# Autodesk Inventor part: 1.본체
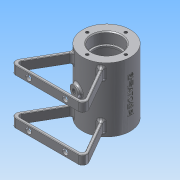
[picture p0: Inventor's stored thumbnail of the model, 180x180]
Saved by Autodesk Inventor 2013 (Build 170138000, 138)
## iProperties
Created: 2016-03
Part Number: 1.본체
Material: 알루미늄 6061
Document SubType Name: Modeling
Designer: Administrator
Mass: 211.191 g
Surface Area: 327.687 cm^2
Volume: 77.9302 cm^3
Density: 2.71 g/cm^3
Author: Administrator
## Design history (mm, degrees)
sketch "스케치1"
  geometry: C1 r 26 at (0, 0); 1 further point
  constraints: 1 centre point, 1 coincident
  dimensions: "d0" = 52 diameter of C1
extrude "돌출1" new body sketch "스케치1" stored distance "d1" = 70; taper "d2" = 0 deg
sketch "스케치2"
  geometry: C1 r 21 at (0, 0); 1 further point
  constraints: 1 centre point, 1 coincident
  dimensions: "d3" = 42 diameter of C1
extrude "돌출2" cut sketch "스케치2" stored distance "d4" = 42; taper "d5" = 0 deg
hole "구멍1" diameter "d8" = 28; stored, may be unused: countersink angle "d12" = 90 deg, drill point angle "d14" = 0 deg; dims "d6" = 10, "d7" = 10, "d9" = 6, "d10" = 32, "d11" = 12, "d13" = 8
hole "구멍2" diameter "d17" = 28; stored, may be unused: countersink angle "d21" = 90 deg, drill point angle "d23" = 0 deg; dims "d15" = 10, "d16" = 10, "d18" = 6, "d19" = 32, "d20" = 12, "d22" = 8
sketch "스케치3"
  geometry: 1 further point
sketch "스케치4" dims "d24" = 42
  geometry: C1 r 26 at (0, 0) reference; 3 further points
  constraints: 2 vertical alignment, 1 coincident, 2 other
hole "구멍3" sketch "스케치4" at (0, 21) diameter "d25" = 3.242; stored, may be unused: countersink angle "d29" = 90 deg, drill point angle "d31" = 118 deg; dims "d26" = 8, "d27" = 32, "d28" = 12, "d30" = 10
sketch "스케치5"
  geometry: 1 further point
node "작업 평면3"
sketch "스케치7"
  geometry: C1 r 5 at (0, 0); 1 further point
  constraints: 1 centre point, 1 coincident
  dimensions: "d37" = 10 diameter of C1
extrude "돌출3" join sketch "스케치7" stored distance "d38" = 42; taper "d39" = 0 deg
sketch "스케치8"
  geometry: C1 r 1.621 at (21, 0) reference; C2 r 1.621 at (0, -21) reference; C3 r 1.621 at (-21, 0) reference; C4 r 1.621 at (0, 21) reference; C5 r 16 at (0, 0) reference; C6 r 26 at (0, 0) reference
node "작업 평면4"
sketch "스케치10"
  geometry: L1 (-14.183, -21.791)-(-37.398, -62); L2 (-37.398, -62)-(37.398, -62); L3 (37.398, -62)-(14.183, -21.791); L4 (16.613, -20)-(42.594, -65); L5 (42.594, -65)-(-42.594, -65); L6 (-42.594, -65)-(-16.613, -20); L7 (0, 0)-(0, -60.192); C1 r 21 at (0, 0) reference; A1 r 26 centre (0, 0) between (-14.183, -21.791) and (14.183, -21.791) reference; 1 further point
  constraints: 14 end point, 4 point on circle, 2 equal length, 2 parallel, 1 horizontal, 1 perpendicular
  dimensions: "d41" = 30 deg angle of L7 L3; "d42" = 30 deg angle of L1 L7; "d43" = 30 deg angle of L7 L6; "d44" = 3 distance between parallel lines of L3 L4; "d46" = 65 distance from line of L5 point (0, 0); "d47" = 3 distance between parallel lines of L2 L5; "d142" = 45 distance from line of L5 L4.start
extrude "돌출4" join sketch "스케치10" distance "d48" = 10; taper "d49" = 0 deg
fillet "모깎기1" dims "d53" = 5, "d54" = 3
hole "구멍4" diameter "d57" = 4.917; stored, may be unused: countersink angle "d61" = 90 deg, drill point angle "d63" = 118 deg; dims "d55" = 10, "d56" = 10, "d58" = 8, "d59" = 32, "d60" = 12, "d62" = 17.75
sketch "스케치13"
  geometry: L1 (0, 0)-(67.868, 0) reference; L2 (0, 10)-(67.868, 10) reference; L3 (33.934, 10)-(33.934, 0); C1 r 3 at (13.934, 5); C2 r 3 at (53.934, 5); 1 further point
  constraints: 2 centre point, 2 end point, 2 midpoint
  dimensions: "d83" = 6 diameter of C1; "d84" = 6 diameter of C2; "d85" = 5 distance from line of L2 C2.centre; "d86" = 40 distance of C1.centre C2.centre; "d87" = 20 distance from line of C1.centre L3
extrude "돌출7" cut sketch "스케치13" stored distance "d88" = 12; taper "d89" = 0 deg
fillet "모깎기2" dims "d90" = 0.5
chamfer "모따기1" distance "d91" = 1; stored, may be unused: second distance "d92" = 2, angle "d93" = 45 deg
fillet "모깎기3" dims "d94" = 0.3
fillet "모깎기4" dims "d95" = 2
fillet "모깎기5" dims "d96" = 3
node "작업 평면5"
sketch "스케치14"
  geometry: L1 (-46.021, -20)-(-42.021, -20) reference; L2 (-41.021, -20.5)-(-41.021, -29.5) reference; L3 (-42.021, -30)-(-46.021, -30) reference; L4 (-41.021, 29.5)-(-41.021, 20.5) reference; L5 (-42.021, 20)-(-46.021, 20) reference; L6 (-46.021, 30)-(-42.021, 30) reference; L7 (26, -35)-(26, 35) reference; L8 (26, -35)-(26, 35) reference; L9 (-47.021, -29.5)-(-47.021, -20.5) reference; L10 (-64.5, -20)-(-62.5, -20) reference; L11 (-62, -20.5)-(-62, -29.5) reference; L12 (-62.5, -30)-(-64.5, -30) reference; L13 (-65, -29.5)-(-65, -20.5) reference; L14 (-64.5, 30)-(-62.5, 30) reference; L15 (-62, 29.5)-(-62, 20.5) reference; L16 (-62.5, 20)-(-64.5, 20) reference; L17 (-65, 20.5)-(-65, 29.5) reference; L18 (-47.021, 20.5)-(-47.021, 29.5) reference; A1 r 0.5 centre (-64.5, -20.5) between (-64.5, -20) and (-65, -20.5) reference; A2 r 0.5 centre (-62.5, -20.5) between (-62, -20.5) and (-62.5, -20) reference; A3 r 0.5 centre (-62.5, -29.5) between (-62.5, -30) and (-62, -29.5) reference; A4 r 0.5 centre (-64.5, -29.5) between (-65, -29.5) and (-64.5, -30) reference; A5 r 0.5 centre (-64.5, 29.5) between (-64.5, 30) and (-65, 29.5) reference; A6 r 0.5 centre (-62.5, 29.5) between (-62, 29.5) and (-62.5, 30) reference; A7 r 0.5 centre (-62.5, 20.5) between (-62.5, 20) and (-62, 20.5) reference; A8 r 0.5 centre (-64.5, 20.5) between (-65, 20.5) and (-64.5, 20) reference; 10 further points; 8 other entities
  constraints: 9 other
  dimensions: "d98" = 0 horizontal distance of point (0, 0) point (0, -0.112); "d99" = 26 distance from line of L7 point (0, -0.112) (derived)
feature "엠보싱1" sketch "스케치14" dims "d100" = 0.5, "d101" = 0
fillet "모깎기6" dims "d105" = 3
sketch "스케치15"
  geometry: 1 further point
sketch "스케치16"
  geometry: L1 (0, 0)-(0, -49.773); L2 (25.89, 2.385)-(26.392, 2.385) reference; L3 (26.371, -2.615)-(25.868, -2.615) reference; L4 (2.458, 20.856)-(2.458, 29) reference; L5 (2.458, 29)-(5, 29) reference; L6 (5, 29)-(5, 27.111) reference; L7 (-5, 27.111)-(-5, 29) reference; L8 (-5, 29)-(-2.458, 29) reference; L9 (-2.458, 29)-(-2.458, 20.856) reference; L10 (-15.167, -21.118)-(-16.377, -25.635); L11 (-16.377, -25.635)-(-4.786, -28.741); L12 (-4.786, -28.741)-(-3.97, -25.695); A1 r 26.5 centre (0, 0) between (26.371, -2.615) and (26.392, 2.385) reference; A2 r 21 centre (0, 0) between (-2.458, 20.856) and (2.458, 20.856) reference; A3 r 26 centre (0, 0) between (25.89, 2.385) and (6.5, 25.174) reference; A4 r 26 centre (0, 0) between (-6.5, 25.174) and (25.868, -2.615) reference
  constraints: 8 end point, 1 parallel, 1 perpendicular, 1 vertical, 2 other
  node "절단 모서리 투영6"
sketch "스케치19"
  geometry: 1 further point
sketch "스케치20"
  geometry: L1 (0, 0)-(0, -41.75); L2 (0, 0)-(-11.03, -41.165); L3 (-7.506, -28.012)-(-1.71, -29.565); L4 (25.89, 2.385)-(26.392, 2.385) reference; L5 (26.371, -2.615)-(25.868, -2.615) reference; L6 (-5, 27.111)-(-5, 29) reference; L7 (-5, 29)-(-2.458, 29) reference; L8 (-2.458, 29)-(-2.458, 20.856) reference; L9 (2.458, 20.856)-(2.458, 29) reference; L10 (2.458, 29)-(5, 29) reference; L11 (5, 29)-(5, 27.111) reference; L12 (-1.71, -29.565)-(-0.752, -25.989); L13 (-7.506, -28.012)-(-13.301, -26.459); L14 (-13.301, -26.459)-(-12.343, -22.883); A1 r 26.5 centre (0, 0) between (26.371, -2.615) and (26.392, 2.385) reference; A2 r 26 centre (0, 0) between (-6.5, 25.174) and (25.868, -2.615) reference; A3 r 21 centre (0, 0) between (-2.458, 20.856) and (2.458, 20.856) reference; A4 r 26 centre (0, 0) between (25.89, 2.385) and (6.5, 25.174) reference
  constraints: 12 end point, 4 perpendicular, 2 point on circle, 1 point on line, 1 vertical, 2 other
  dimensions: "d122" = 15 deg angle of L1 L2; "d123" = 6 distance between parallel lines of L12 L2; "d125" = 29 distance from line of L13 L1.start; "d126" = 6 distance between parallel lines of L14 L2
extrude "돌출10" join sketch "스케치20" stored distance "d127" = 12; taper "d128" = 0 deg
sketch "스케치21"
  geometry: L1 (0, 0)-(0, 12) reference; L2 (-12, 12)-(0, 12) reference; L3 (-12, 0)-(-12, 12) reference; L4 (0, 0)-(-12, 0) reference; C1 r 6 at (-6, 6); 1 further point
  constraints: 1 centre point, 1 coincident
  dimensions: "d129" = 12 diameter of C1
extrude "돌출11" cut sketch "스케치21" stored distance "d130" = 12; taper "d131" = 0 deg
hole "구멍6" diameter "d134" = 4.917; stored, may be unused: countersink angle "d138" = 90 deg, drill point angle "d140" = 0 deg; dims "d132" = 10, "d133" = 10, "d135" = 8, "d136" = 32, "d137" = 12, "d139" = 17.75
fillet "모깎기7" dims "d141" = 2
sketch "스케치17"
  geometry: L1 (25.89, 2.385)-(26.392, 2.385) reference; L2 (26.371, -2.615)-(25.868, -2.615) reference; L3 (13.836, -23.656)-(14.501, -26.138) reference; L4 (14.501, -26.138)-(11.08, -27.054) reference; L5 (11.08, -27.054)-(8.924, -19.009) reference; L6 (2.458, 20.856)-(2.458, 29) reference; L7 (2.458, 29)-(5, 29) reference; L8 (5, 29)-(5, 27.111) reference; L9 (-5, 27.111)-(-5, 29) reference; L10 (-5, 29)-(-2.458, 29) reference; L11 (-2.458, 29)-(-2.458, 20.856) reference; L12 (4.251, -20.565)-(6.331, -28.327) reference; L13 (6.331, -28.327)-(2.91, -29.243) reference; L14 (2.91, -29.243)-(2.437, -27.478) reference; L15 (0, 0)-(0, -44.249); L16 (-7.597, -28.353)-(0, 0); L17 (-7.597, -28.353)-(-1.802, -29.906); L18 (-7.597, -28.353)-(-13.393, -26.8); L19 (-13.393, -26.8)-(-12.343, -22.883); L20 (-1.802, -29.906)-(-0.752, -25.989); A1 r 26.5 centre (0, 0) between (26.371, -2.615) and (26.392, 2.385) reference; A2 r 26 centre (0, 0) between (14.641, -21.486) and (25.868, -2.615) reference; A3 r 21 centre (0, 0) between (8.924, -19.009) and (2.458, 20.856) reference; A4 r 26 centre (0, 0) between (25.89, 2.385) and (6.5, 25.174) reference; A5 r 26 centre (0, 0) between (-6.5, 25.174) and (0.469, -25.996) reference; A6 r 21 centre (0, 0) between (-2.458, 20.856) and (4.251, -20.565) reference; 1 further point
  constraints: 12 end point, 2 parallel, 2 perpendicular, 2 point on circle, 1 collinear, 4 other
  dimensions: "d111" = 29.35309 distance of L16.start L15.start; "d112" = 15 deg angle of L16 L15; "d115" = 6 distance of L16.start L18.end; "d116" = 6 distance of L16.start L17.end
extrude "돌출8" join sketch "스케치17" stored distance "d117" = 12; taper "d118" = 0 deg
sketch "스케치18"
  geometry: L1 (0, 0)-(0, 12) reference; L2 (-12, 12)-(0, 12) reference; L3 (-12, 0)-(-12, 12) reference; L4 (0, 0)-(-12, 0) reference; C1 r 6 at (-6, 6); 1 further point
  constraints: 1 centre point, 1 coincident
  dimensions: "d119" = 12 diameter of C1
extrude "돌출9" cut sketch "스케치18" stored distance "d120" = 12; taper "d121" = 0 deg
node "솔리드1"
pattern_circular "원형 패턴1" dims angle "d33" = 360 deg
pattern_circular "원형 패턴2" dims angle "d51" = 360 deg
pattern_linear "직사각형 패턴1" dims "d104" = 50
node "절단 모서리 투영3"
node "절단 모서리 투영5"
node "절단 모서리 투영7"
node "절단 모서리 투영8"
other parameters: "d36" = 29, "d97" = 28.75
